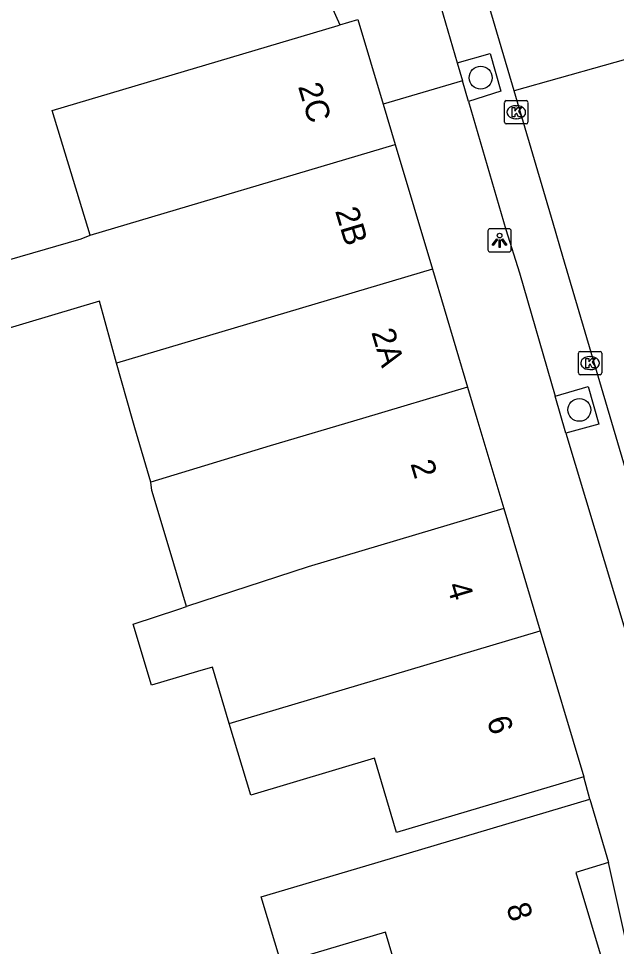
# Model space of a CAD drawing. Extents: x 159377 to 159983, y 382996 to 383595.
# Drawn here: x 159627.86 to 159653.42, y 383477.41 to 383517.11 of the extents above; entities that cross this region are included whole.
import ezdxf

# ---------------------------------------------------------------- set-up
doc = ezdxf.new("R2010")
doc.units = 0
for name, color, linetype in [('IMGEO_Boom', 7, 'Continuous'), ('IMGEO_Kolk', 7, 'Continuous'), ('IMGEO_Lichtpunt', 7, 'Continuous'), ('IMGEO_Pand', 7, 'Continuous'), ('IMGEO_Pand_nummerreeks', 7, 'Continuous'), ('IMGEO_Parkeervlak_open', 7, 'Continuous'), ('IMGEO_Rijbaan_lokaal_gesloten', 7, 'Continuous'), ('IMGEO_Rijbaan_lokaal_open', 7, 'Continuous'), ('IMGEO_Voetpad_open', 7, 'Continuous')]:
    doc.layers.add(name, color=color, linetype=linetype)

msp = doc.modelspace()

# ---------------------------------------------------------------- linework, layer by layer
at = {"layer": 'IMGEO_Boom'}
for centre in [(159647.614, 383514.583), (159651.834, 383500.369)]:
    msp.add_circle(centre, 0.489, dxfattribs=at)
at = {"layer": 'IMGEO_Kolk'}
for p, q in [((159648.636, 383512.677), (159648.636, 383513.529)), ((159648.711, 383513.603), (159649.563, 383513.603)), ((159649.637, 383513.529), (159649.637, 383512.677)), ((159649.124, 383513.383), (159649.149, 383513.383)), ((159649.147, 383512.823), (159649.122, 383512.823)), ((159649.563, 383512.603), (159648.711, 383512.603)), ((159651.791, 383501.947), (159651.791, 383502.799)), ((159651.866, 383502.873), (159652.718, 383502.873)), ((159652.792, 383502.799), (159652.792, 383501.947)), ((159652.279, 383502.653), (159652.304, 383502.653)), ((159652.302, 383502.093), (159652.277, 383502.093)), ((159652.718, 383501.873), (159651.866, 383501.873))]:
    msp.add_line(p, q, dxfattribs=at)
for points in [[(159648.636, 383512.677), (159648.636, 383513.529)], [(159648.711, 383513.603), (159649.563, 383513.603)], [(159649.637, 383513.529), (159649.637, 383512.677)], [(159648.957, 383513.303), (159649.08, 383513.303), (159649.08, 383513.152), (159649.21, 383513.303), (159649.374, 383513.303), (159649.228, 383513.152), (159649.381, 383512.903), (159649.229, 383512.903), (159649.144, 383513.067), (159649.08, 383513), (159649.08, 383512.903), (159648.957, 383512.903), (159648.957, 383513.303)], [(159649.563, 383512.603), (159648.711, 383512.603)], [(159651.791, 383501.947), (159651.791, 383502.799)], [(159651.866, 383502.873), (159652.718, 383502.873)], [(159652.792, 383502.799), (159652.792, 383501.947)], [(159652.112, 383502.573), (159652.235, 383502.573), (159652.235, 383502.422), (159652.365, 383502.573), (159652.529, 383502.573), (159652.383, 383502.422), (159652.536, 383502.173), (159652.384, 383502.173), (159652.299, 383502.337), (159652.235, 383502.27), (159652.235, 383502.173), (159652.112, 383502.173), (159652.112, 383502.573)], [(159652.718, 383501.873), (159651.866, 383501.873)]]:
    msp.add_lwpolyline(points, dxfattribs=at)
for centre, start, end in [((159648.713, 383513.527), 91.552, 178.448), ((159648.713, 383513.527), 91.552, 178.448), ((159649.561, 383513.527), 1.552, 88.448), ((159649.561, 383513.527), 1.552, 88.448), ((159648.713, 383512.679), 181.552, 268.448), ((159648.713, 383512.679), 181.552, 268.448), ((159649.561, 383512.679), 271.552, 358.448), ((159649.561, 383512.679), 271.552, 358.448), ((159651.868, 383502.797), 91.552, 178.448), ((159651.868, 383502.797), 91.552, 178.448), ((159652.716, 383502.797), 1.552, 88.448), ((159652.716, 383502.797), 1.552, 88.448), ((159651.868, 383501.949), 181.552, 268.448), ((159651.868, 383501.949), 181.552, 268.448), ((159652.716, 383501.949), 271.552, 358.448), ((159652.716, 383501.949), 271.552, 358.448)]:
    msp.add_arc(centre, 0.0765, start, end, dxfattribs=at)
for centre, major_axis, ratio, start_param, end_param in [((159649.123, 383513.103), (-0.387, 0.002), 0.722429, 4.712389, 7.853982), ((159649.148, 383513.103), (-0.39, 0.002), 0.717154, 1.570796, 4.712389), ((159652.278, 383502.373), (-0.387, 0.002), 0.722429, 4.712389, 7.853982), ((159652.303, 383502.373), (-0.39, 0.002), 0.717154, 1.570796, 4.712389)]:
    msp.add_ellipse(centre, major_axis=major_axis, ratio=ratio, start_param=start_param, end_param=end_param, dxfattribs=at)
at = {"layer": 'IMGEO_Lichtpunt'}
for p, q in [((159647.925, 383508.027), (159647.925, 383507.22)), ((159647.925, 383508.027), (159647.925, 383507.22)), ((159648.827, 383508.122), (159648.019, 383508.122)), ((159648.827, 383508.122), (159648.019, 383508.122)), ((159648.921, 383507.22), (159648.921, 383508.027)), ((159648.921, 383507.22), (159648.921, 383508.027)), ((159648.019, 383507.126), (159648.827, 383507.126)), ((159648.019, 383507.126), (159648.827, 383507.126))]:
    msp.add_line(p, q, dxfattribs=at)
for points in [[(159648.299, 383507.691), (159648.338, 383507.663), (159648.15, 383507.401), (159648.112, 383507.428), (159648.299, 383507.691)], [(159648.401, 383507.643), (159648.448, 383507.643), (159648.448, 383507.321), (159648.401, 383507.321), (159648.401, 383507.643)], [(159648.511, 383507.663), (159648.549, 383507.69), (159648.736, 383507.428), (159648.697, 383507.4), (159648.511, 383507.663)]]:
    msp.add_lwpolyline(points, dxfattribs=at)
msp.add_circle((159648.424, 383507.825), 0.0994, dxfattribs=at)
for centre, start, end in [((159648.019, 383508.027), 90, 180), ((159648.019, 383508.027), 90, 180), ((159648.827, 383508.027), 0, 90), ((159648.827, 383508.027), 0, 90), ((159648.019, 383507.22), 180, 270), ((159648.019, 383507.22), 180, 270), ((159648.827, 383507.22), 270, 0), ((159648.827, 383507.22), 270, 360)]:
    msp.add_arc(centre, 0.0946, start, end, dxfattribs=at)
at = {"layer": 'IMGEO_Pand'}
for points in [[(159630.263, 383553.702), (159639.093, 383533.207), (159636.546, 383532.137), (159638.413, 383527.811), (159639.238, 383528.162), (159641.943, 383521.796), (159640.758, 383521.313), (159640.819, 383521.158), (159640.755, 383521.129), (159639.852, 383520.736), (159641.59, 383516.842)], [(159641.59, 383516.842), (159642.369, 383517.075), (159643.446, 383513.457)], [(159630.914, 383507.842), (159629.745, 383511.675), (159629.296, 383513.184), (159641.528, 383516.824), (159641.59, 383516.842)], [(159643.446, 383513.457), (159643.961, 383511.727)], [(159630.914, 383507.842), (159643.961, 383511.727)], [(159643.961, 383511.727), (159645.553, 383506.383)], [(159625.3, 383506.17), (159630.531, 383507.69), (159630.914, 383507.842)], [(159645.553, 383506.383), (159632.051, 383502.361)], [(159645.553, 383506.383), (159647.055, 383501.337)], [(159632.051, 383502.361), (159631.324, 383505.024), (159626.104, 383503.47), (159625.3, 383506.17)], [(159633.517, 383497.27), (159632.823, 383499.6), (159632.711, 383500), (159632.051, 383502.361)], [(159647.055, 383501.337), (159642.564, 383500), (159638.617, 383498.825), (159633.517, 383497.27)], [(159647.055, 383501.337), (159647.453, 383500), (159648.601, 383496.143)], [(159635.041, 383491.952), (159634.337, 383494.314), (159633.561, 383496.919), (159633.517, 383497.27)], [(159648.601, 383496.143), (159640.242, 383493.654), (159635.041, 383491.952)], [(159648.601, 383496.143), (159650.159, 383490.911)], [(159636.868, 383486.953), (159636.152, 383489.36), (159635.511, 383489.169), (159633.541, 383488.582), (159632.761, 383491.203), (159634.715, 383491.843), (159635.041, 383491.952)], [(159636.868, 383486.953), (159650.159, 383490.911)], [(159650.159, 383490.911), (159652.02, 383484.662)], [(159652.02, 383484.662), (159644.018, 383482.28), (159643.071, 383485.461), (159637.781, 383483.886), (159636.868, 383486.953)], [(159644.76, 383473.936), (159643.545, 383478.019), (159639.081, 383476.69), (159638.236, 383479.531), (159642.699, 383480.86), (159652.275, 383483.712)], [(159652.275, 383483.712), (159653.084, 383480.993)], [(159653.084, 383480.993), (159651.686, 383480.577), (159652.938, 383476.371), (159644.76, 383473.936)]]:
    msp.add_lwpolyline(points, dxfattribs=at)
at = {"layer": 'IMGEO_Parkeervlak_open'}
for points in [[(159646.608, 383515.216), (159648.021, 383515.624), (159648.48, 383514), (159647.09, 383513.567)], [(159650.804, 383500.962), (159652.215, 383501.375), (159652.671, 383499.762), (159651.26, 383499.365)]]:
    msp.add_lwpolyline(points, dxfattribs=at)
at = {"layer": 'IMGEO_Rijbaan_lokaal_gesloten'}
for points in [[(159654.814, 383515.652), (159649.044, 383514.017)], [(159658.876, 383480.639), (159651.133, 383506.926), (159650.711, 383508.356), (159649.044, 383514.017)]]:
    msp.add_lwpolyline(points, dxfattribs=at)
at = {"layer": 'IMGEO_Rijbaan_lokaal_open'}
msp.add_lwpolyline([(159649.044, 383514.017), (159643.547, 383532.683)], dxfattribs=at)
at = {"layer": 'IMGEO_Voetpad_open'}
for points in [[(159643.547, 383532.683), (159641.653, 383532.125), (159645.106, 383520.362), (159646.608, 383515.216)], [(159646.608, 383515.216), (159646.834, 383514.444)], [(159646.834, 383514.444), (159643.446, 383513.457)], [(159647.09, 383513.567), (159646.834, 383514.444)], [(159647.09, 383513.567), (159648.688, 383508.093), (159649.269, 383506.238), (159650.804, 383500.962)], [(159651.26, 383499.365), (159650.804, 383500.962)], [(159651.26, 383499.365), (159656.215, 383482.877)], [(159652.275, 383483.712), (159652.02, 383484.662)], [(159654.869, 383472.918), (159653.084, 383480.993)]]:
    msp.add_lwpolyline(points, dxfattribs=at)

# ---------------------------------------------------------------- texts
at = {"layer": 'IMGEO_Pand_nummerreeks'}
for s, rotation, p in [('2C', 286.5812, (159639.8, 383514.211)), ('2B', 286.5856, (159641.384, 383508.889)), ('2A', 286.5762, (159642.932, 383503.695)), ('2', 286.5757, (159644.605, 383498.07)), ('4', 286.5812, (159646.159, 383492.854)), ('6', 286.5839, (159647.867, 383487.114)), ('8', 286.5767, (159648.699, 383479.116))]:
    msp.add_text(s, height=1, rotation=rotation, dxfattribs=at).set_placement(p)

doc.saveas('drawing.dxf')
